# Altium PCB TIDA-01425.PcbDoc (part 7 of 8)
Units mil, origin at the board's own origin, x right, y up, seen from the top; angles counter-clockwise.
Board outline 7000 x 3600 mil, 6 copper layers (Layer 1 - Top Layer, Layer 2 - GND, Layer 3 - Signal / PWR, Layer 4 - Signal / PWR, Layer 5 - PWR, Layer 6 - Bottom Layer), stack 60.4 mil thick; 495 components, 307 nets, 2058 pads, 1870 vias.
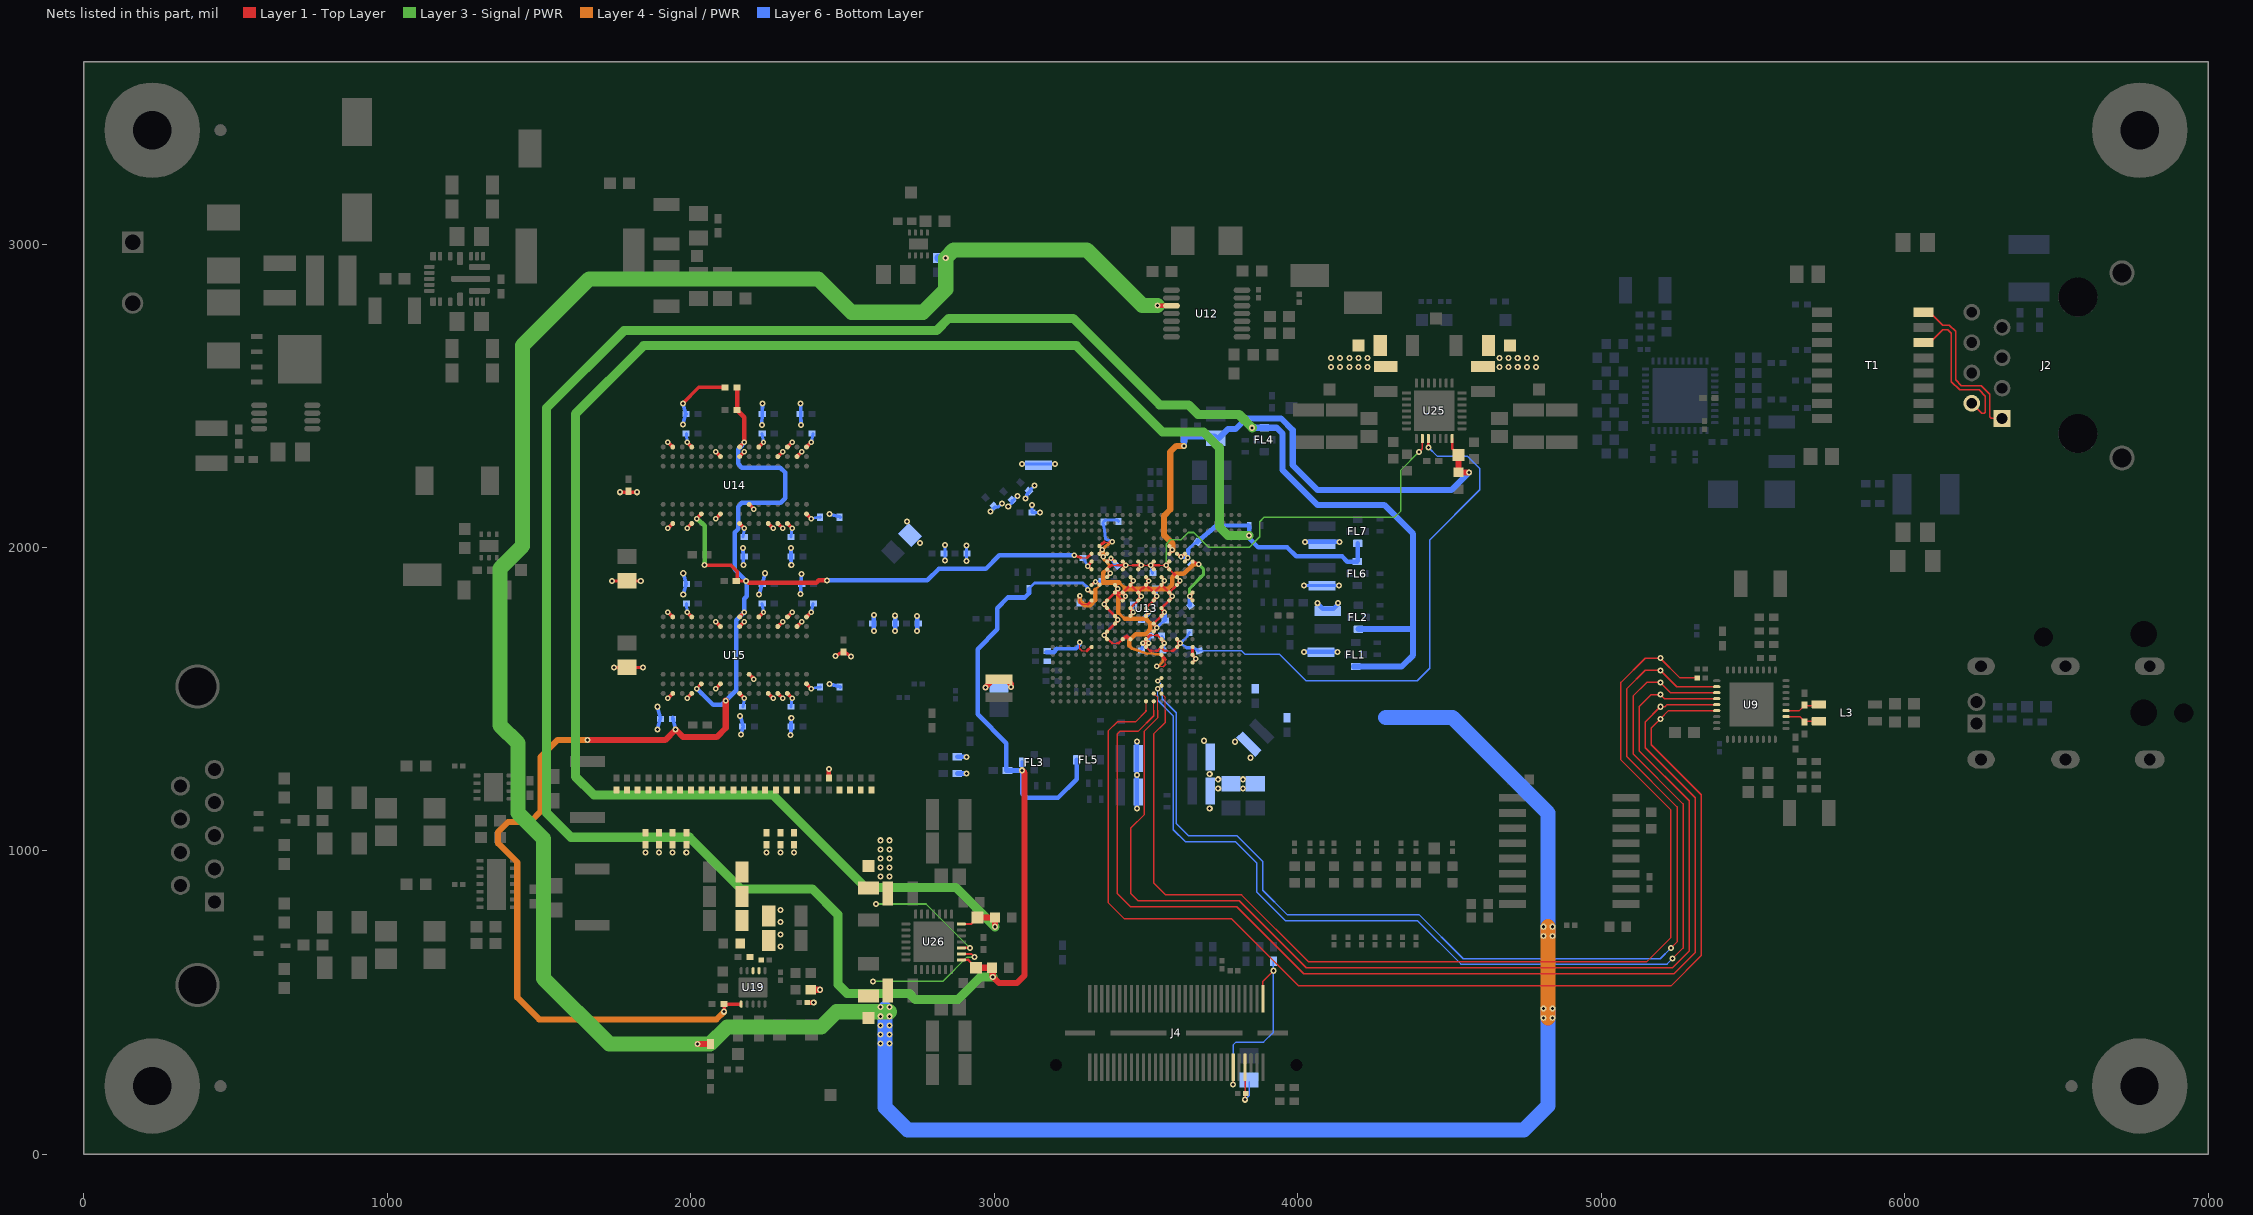
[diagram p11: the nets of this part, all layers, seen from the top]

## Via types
v1: diameter 20, hole 10, Layer 1 - Top Layer to Layer 6 - Bottom Layer, tented both sides, 1119 vias
v2: diameter 20, hole 9.99, Layer 1 - Top Layer to Layer 6 - Bottom Layer, tented both sides, 298 vias
v3: diameter 18, hole 7.99, Layer 1 - Top Layer to Layer 6 - Bottom Layer, tented both sides, 203 vias
v4: diameter 18, hole 8, Layer 1 - Top Layer to Layer 6 - Bottom Layer, tented both sides, 177 vias
v5: diameter 19.68, hole 7.87, Layer 1 - Top Layer to Layer 6 - Bottom Layer, tented both sides, 41 vias
v6: diameter 20, hole 10, Layer 1 - Top Layer to Layer 6 - Bottom Layer, 27 vias
v7: diameter 19.68, hole 7.87, Layer 1 - Top Layer to Layer 6 - Bottom Layer, 5 vias

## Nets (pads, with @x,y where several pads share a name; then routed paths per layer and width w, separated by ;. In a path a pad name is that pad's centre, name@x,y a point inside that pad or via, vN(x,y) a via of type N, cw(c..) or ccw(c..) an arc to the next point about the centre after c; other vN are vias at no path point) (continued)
TRD1_N: L3.2 U9.13 U10.1 | length 114.8
  Layer 1 - Top Layer w5: U9.13@5609.17,1462.32 5653.31,1462.32 5670,1479 L3.2@5713.92,1479
  Layer 1 - Top Layer w8: L3.2@5715.24,1480.32 L3.2@5717.48,1482.56
TRD1_P: L3.3 U9.12 U11.1 | length 114.6
  Layer 1 - Top Layer w5: U9.12@5609.17,1442.63 5654.37,1442.63 5669.56,1427.44 L3.3@5717.48,1427.44
TRSTPD: J4.8 R57.2 R58.2 | length 172.8
  Layer 1 - Top Layer w5: v1(3826.38,180) J4.8@3826.38,287.21
  Layer 6 - Bottom Layer w5: v1(3826.38,180) 3840,193.62 R58.2@3840,240
TX+: J2.1 T1.16 | length 541.1
  Layer 1 - Top Layer w4.4: T1.16@6062.52,2775 6083,2775 6126,2732 6147.8,2732 6168,2711.8 6168,2552 6187,2533 6251.8,2533 6280,2504.8 6280,2430 6285,2425 J2.1@6321.26,2425
TX-: J2.2 T1.14 | length 518.7
  Layer 1 - Top Layer w4.4: T1.14@6062.52,2675 6082,2675 6125,2718 6142,2718 6154,2706 6154,2546.2 6181.2,2519 6246,2519 6266,2499 6266,2446 6262,2442 6254.26,2442 J2.2@6221.26,2475
TX_CLK_1: R25.1 U13.B11 | length 3711.9
  Layer 1 - Top Layer w4: U13.B11@3551.18,1518.5 3563.87,1505.81 3563.87,1464
  Layer 1 - Top Layer w5: 3563.87,1464 3563.87,1423.87 3525,1385 3525,895 3565,855 3815,855 4036,634 5149,634 5230,715 5230,1135 5065,1300 5065,1555 5145,1635 v6(5195,1635) 5260,1570 R25.1@5317.01,1570
TX_CTRL_1: U9.29 U13.D11 | length 3671
  Layer 1 - Top Layer w4: v3(3538.6,1559.9) U13.D11@3551.18,1569.69
  Layer 1 - Top Layer w5: v1(5230,680) 5250,700 5250,1145 5085,1310 5085,1535 5145,1595 v6(5195,1595) 5248.94,1541.06 U9.29@5380.83,1541.06
  Layer 6 - Bottom Layer w4: v3(3538.6,1559.9) 3539.1,1559.9 3553.59,1545.41 3553.59,1523.6
  Layer 6 - Bottom Layer w5: 3553.59,1523.6 3553.59,1501.41 3600,1455 3600,1090 3640,1050 3800,1050 3885,965 3885,870 3965,790 4400,790 4545.36,644.64 5194.64,644.64 v1(5230,680)
TX_D0_1: U9.33 U13.A13 | length 3918.1
  Layer 1 - Top Layer w4: 3500,1464 U13.A13@3500,1492.91
  Layer 1 - Top Layer w5: 3500,1464 3500,1460 3465,1425 3405,1425 3375,1395 3375,830 3429,776 3782.28,776 4003.28,555 5230,555 5330,655 5330,1185 5165,1350 5165,1405 v6(5195,1435) 5222.31,1462.32 U9.33@5380.83,1462.32
TX_D1_1: U9.32 U13.A12 | length 3849.5
  Layer 1 - Top Layer w4: 3525.59,1464 U13.A12@3525.59,1492.91
  Layer 1 - Top Layer w5: 3525.59,1464 3525.59,1445.59 3475,1395 3415,1395 3405,1385 3405,860 3449,816 3798.85,816 4019.85,595 5240,595 5310,665 5310,1175 5145,1340 5145,1425 v6(5195,1475) 5210,1475 5217,1482 U9.32@5380.83,1482
TX_D2_1: U9.31 U13.B12 | length 3815.8
  Layer 1 - Top Layer w4: U13.B12@3525.59,1518.5 3538.28,1505.81 3538.28,1464
  Layer 1 - Top Layer w5: 3538.28,1464 3538.28,1438.28 3495,1395 3495,1120 3450,1075 3450,860 3474,836 3807.13,836 4028.13,615 5235,615 5290,670 5290,1165 5125,1330 5125,1475 5165,1515 v6(5195,1515) 5208.31,1501.68 U9.31@5380.83,1501.68
TX_D3_1: U9.30 U13.C11 | length 3649.3
  Layer 1 - Top Layer w4: v3(3538.6,1534) U13.C11@3551.18,1544.09
  Layer 1 - Top Layer w5: v1(5235,645) 5270,680 5270,1155 5105,1320 5105,1510 5150,1555 v6(5195,1555) 5228.63,1521.37 U9.30@5380.83,1521.37
  Layer 6 - Bottom Layer w4: 3538.6,1512.06 v3(3538.6,1534)
  Layer 6 - Bottom Layer w5: 3538.6,1512.06 3538.6,1496.4 3590,1445 3590,1070 3630,1030 3795,1030 3865,960 3865,865 3960,770 4395,770 4538.03,626.97 5216.97,626.97 v1(5235,645)
VDA_PHY_1V8: C59.1 C64.1 C268.1 FL6.1 FL7.1 TP62.1 U13.W8 U13.Y8 U13.Y9 U26.7 | length 6491.1
  Layer 1 - Top Layer w8: U26.7@2891.54,759.06 2924.06,759.06 TP62.1@2945,780
  Layer 1 - Top Layer w10: U13.Y9@3602.41,1979.19 v3(3615.3,1969.2) 3627.94,1979.15 3628,1979.2 v3(3638,1966.5) U13.W8@3628,1953.6
  Layer 1 - Top Layer w20: TP62.1@2945,780 C268.1@3002.44,780 v2(3002.44,750)
  Layer 3 - Signal / PWR w30: v2(3002.44,750) 2872.44,880 2575,880 2270.43,1184.57 1680.43,1184.57 1620,1245 1620,2440 1845,2665 3270,2665 3555,2380 3690,2380 3741.59,2328.41 3741.59,2068.41 3770,2040 v1(3840,2040)
  Layer 6 - Bottom Layer w10: 3638.5,1992 3642.3,1997.8 3656.5,2010.2 3668,2018.1 C59.1@3668.28,2017.79
  Layer 6 - Bottom Layer w15: v3(3615.3,1969.2) v3(3638,1966.5) 3638.5,1992 ; C59.1@3668.28,2017.79 3668.92,2018.32 3733.1,2072.2 3834.98,2072.79 3836.6,2072.8 3840,2069.4 3840,2030 3870,2000 3966,2000 3995,1971 4146,1971 4163.63,1953.37 FL6.1@4196,1953.37 4198,1955.37 FL7.1@4198,2013.63
VDA_PLL_1V8: C32.1 C33.1 C267.1 FL1.1 FL2.1 FL3.1 FL4.1 FL5.1 TP61.1 U13.R20 U26.1 | length 9704.2
  Layer 1 - Top Layer w8: U26.1@2891.54,640.94 2914.06,640.94 TP61.1@2940,615 TP61.1@2945,615
  Layer 1 - Top Layer w10: v3(3308,1860.8) U13.R20@3320.8,1851.2
  Layer 1 - Top Layer w20: TP61.1@2945,615 C267.1@2992.44,615 2995,612.44 v2(2995,585) 3015,565 3075,565 3100,590 3100,1257.4 v2(3091.7,1265.7)
  Layer 3 - Signal / PWR w30: v2(2995,585) 2955,585 2880,510 2740,510 2720,530 2515,530 2485,560 2485,790 2400,875 2165,875 1995,1045 1605,1045 1525,1125 1525,2460 1780,2715 2810,2715 2850,2755 3260,2755 3545,2470 3640,2470 3672,2438 3806.37,2438 v1(3850,2394.37)
  Layer 6 - Bottom Layer w10: v2(3091.7,1265.7) FL3.1@3091.7,1295 ; C33.1@3114.6,1864.6 3132.81,1882.81 3292.24,1882.81 3308,1867.05 v3(3308,1860.8)
  Layer 6 - Bottom Layer w15: C33.1@3114.6,1864.6 3114.6,1849.6 3100,1835 3045,1835 3010,1800 3010,1730 2945,1665 2945,1450 3040,1355 3040,1265 3091,1265 v2(3091.7,1265.7) 3091.7,1188.3 3105,1175 3210,1175 3271.63,1236.63 FL5.1@3271.63,1300
  Layer 6 - Bottom Layer w20: v1(3850,2394.37) FL4.1@3890,2394.37 3930.63,2394.37 3950,2375 3950,2255 4065,2140 4285,2140 4380,2045 4380,1730.63 FL2.1@4200,1730.63 ; FL1.1@4185,1607.63 FL1.1@4191,1607.63 4342.63,1607.63 4380,1645 4380,1727.63
VDA_USB_3V3: C49.1 C58.1 C60.1 C250.1 TP54.1 U13.AA10 U13.Y10 U25.7 | length 1768
  Layer 1 - Top Layer w8: U25.7@4509.06,2358.46 4509.06,2325.94 TP54.1@4530,2305
  Layer 1 - Top Layer w10: U13.Y10@3576.77,1979.13 v3(3586.8,1992.2) U13.AA10@3576.77,2004.72
  Layer 1 - Top Layer w20: TP54.1@4530,2305 C250.1@4530,2247.56 v2(4565,2247.56)
  Layer 4 - Signal / PWR w20: v3(3586.8,1992.2) 3586.8,2013.2 3560,2040 3560,2105 3580,2125 3580,2315 3600,2335 v2(3625,2335)
  Layer 6 - Bottom Layer w20: v2(3625,2335) C49.1@3625,2361.38 ; C49.1@3625,2361.38 3628.62,2365 C58.1@3670,2365 3725,2365 C60.1@3730,2360 3740,2360 3770,2390 3795,2390 3830,2425 3945,2425 3983.5,2386.5 3983.5,2271.5 4065,2190 4507.44,2190 v2(4565,2247.56)
VDD_CORE_AVS: C9.1 C10.1 C21.1 C27.1 C94.1 C95.1 C96.1 C97.1 C102.1 C240.1 L2.2 TP51.1 U13.J15 U13.J16 U13.J18 U13.K12 U13.K18 U13.L12 U13.L17 U13.M11 U13.M13 U13.M15 U13.M17 U13.N11 U13.N13 U13.N15 U13.N18 U13.P10 U13.P12 U13.P14 U13.P16 U13.P18 U13.R10 U13.R12 U13.R14 U13.R16 U13.R17 U13.T9 U13.T11 U13.T13 U13.T15 U13.T17 U13.U9 U13.U11 U13.U13 U13.U15 U13.U18 U13.V10 U13.V12 U13.V14 U13.V16 U13.V18 U13.W10 U13.W12 U13.W14 U13.W16 U25.2 | length 3423.4
  Layer 1 - Top Layer w4: 3389.16,1684.35 3389.55,1684.74 3405.73,1684.74 ; 3389.66,1940.76 3405,1940.76 ; v3(3433.3,1940.9) 3433.35,1940.85 3456.91,1940.85 ; v3@3492.2,1940.8 v3@3507.4,1940.8 ; U13.R12@3525.59,1851.18 3525.68,1851.09 3535,1841.77 v3(3535,1838.5) ; 3543.22,1940.8 v3@3558.5,1940.8
  Layer 1 - Top Layer w6: v2(4400,2315) 4410.63,2325.63 U25.2@4410.63,2358.46
  Layer 1 - Top Layer w8: U13.J18@3372.05,1697.64 3389.15,1684.35 ; U13.K18@3372.05,1723.23 U13.L17@3397.64,1748.82 ; U13.N18@3372.05,1800 U13.M17@3397.64,1774.41 ; U13.P18@3372.05,1825.59 U13.R17@3397.64,1851.18 ; U13.V18@3372.05,1927.95 3384.86,1940.76 3389.66,1940.76 ; 3405,1940.76 3433.16,1940.76 v3(3433.3,1940.9) v3@3440.68,1940.9 ; 3405.73,1684.74 3410.33,1684.74 U13.J16@3423.23,1697.64 ; U13.R16@3423.23,1851.18 U13.R17@3397.64,1851.18 ; U13.R16@3423.25,1851.2 U13.T15@3448.82,1876.77 U13.R14@3474.41,1851.18 U13.T13@3500,1876.77 U13.R12@3525.59,1851.18 U13.T11@3551.18,1876.77 U13.R10@3576.77,1851.18 U13.R10@3576.77,1851.18 U13.T9@3602.36,1876.77 ; v3(3432.5,1838.5) 3432.5,1834.86 U13.P16@3423.23,1825.59 U13.R17@3397.64,1851.18 ; U13.N15@3448.82,1800 U13.P14@3474.41,1825.59 ; 3456.91,1940.85 v3(3484.2,1940.8) v3(3484.2,1940.8) v3@3492.2,1940.8 ; U13.N13@3500,1800 U13.P12@3525.59,1825.59 ; v3@3507.4,1940.8 v3(3516,1940.8) 3543.22,1940.8 ; U13.L12@3525.59,1748.82 U13.M11@3551.18,1774.41 ; U13.N11@3551.18,1800 U13.P10@3576.77,1825.59 ; v3@3558.5,1940.8 3558.6,1940.9 v3(3567.2,1940.9) ; U13.V10@3576.77,1927.95 3602.32,1902.4 U13.U9@3602.36,1902.36
  Layer 1 - Top Layer w10: U13.J18@3372.05,1697.64 v3(3362.3,1710.4) U13.K18@3372.05,1723.23 ; U13.U18@3372.05,1902.36 3382,1913.4 v3(3382,1915.1) U13.V18@3372.05,1927.95 ; U13.V16@3423.23,1927.95 v3(3433.3,1940.9) U13.W16@3423.23,1953.54 ; U13.T15@3448.82,1876.77 v3(3458.3,1889.8) U13.U15@3448.82,1902.36 ; U13.V14@3474.41,1927.95 v3(3484.2,1940.8) U13.W14@3474.43,1953.56 ; U13.T13@3500,1876.77 v3(3509.4,1889.4) U13.U13@3500,1902.36 ; U13.R12@3525.59,1851.18 3525.68,1851.09 v3(3535,1838.5) ; U13.V12@3525.59,1927.95 v3(3516,1940.8) U13.W12@3525.59,1953.54 ; U13.T11@3551.18,1876.77 v3(3560.9,1889.6) U13.U11@3551.18,1902.36 ; U13.V10@3576.77,1927.95 v3(3567.2,1940.9) U13.W10@3576.77,1953.54 ; U13.T9@3602.36,1876.77 v3(3612.06,1889.89) U13.U9@3602.36,1902.36
  Layer 1 - Top Layer w12: U13.N18@3372.05,1800 v3(3362,1813) U13.P18@3372.05,1825.59 ; U13.L17@3397.64,1748.82 v3(3407,1761.5) U13.M17@3397.64,1774.41 ; U13.R17@3397.64,1851.18 v3(3407,1864) U13.T17@3397.64,1876.77 ; U13.R16@3423.23,1851.18 v3(3432.5,1838.5) ; U13.J16@3423.23,1697.64 3436,1707 U13.J15@3448.82,1697.64 ; U13.M15@3448.82,1774.41 v3(3458.5,1787) U13.N15@3448.82,1800 ; U13.P14@3474.41,1825.59 v3(3483.7,1838.5) U13.R14@3474.41,1851.18 ; U13.M13@3500,1774.41 v3(3509.5,1787.5) U13.N13@3500,1800 ; U13.K12@3525.59,1723.23 v3(3535,1736) U13.L12@3525.59,1748.82 ; U13.P12@3525.59,1825.59 v3(3535,1838.5) ; U13.M11@3551.18,1774.41 v3(3561,1787) U13.N11@3551.18,1800 ; U13.P10@3576.77,1825.59 v3(3586.1,1838.5) U13.R10@3576.77,1851.18
  Layer 3 - Signal / PWR w5.25: v3(3567.2,1940.9) 3567.2,2012.2 3580,2025 3615,2025 3639.15,2049.15 3657.46,2049.15 3706.61,2000 3840,2000 3875,2035 3875,2085 3890,2100 4320,2100 4340,2120 4340,2255 v2(4400,2315)
  Layer 6 - Bottom Layer w10: C102.1@3457.5,1812.5 3457.53,1811.92 v3(3458.5,1787) ; v3(3516,1940.8) 3521.82,1915.8 C95.1@3522,1915 ; C97.1@3533,1863.5 v3(3535,1838.5) ; v3(3535,1736) 3545.15,1745.1 3554.04,1753.99 3555.07,1753.99 3562.83,1760.95 C96.1@3564,1762 ; v2(4021.2,1874.3) 4021.5,1874 v2(4136,1874)
  Layer 6 - Bottom Layer w15: C94.1@3488,1762 3509.5,1783.5 v3(3509.5,1787.5) ; v3(3561,1787) 3561,1765 C96.1@3564,1762 ; v2@4021.2,1655.8 v2(4131.6,1655.8) ; v1@4024,2018.1 v2(4137.1,2018.1) ; v2(4064.8,1816.2) 4083,1798 4117.9,1798 4132.9,1813 v2(4132.9,1817.3)
  other v1: 4024,2018
  other v2: 4021,1656 4110,2595 4140,2595 4170,2595 4200,2595 4230,2595 4110,2625 4140,2625 4170,2625 4200,2625 4230,2625
VDD_DDR_1V35: C61.1 C63.1 C65.1 C66.1 C67.1 C68.1 C69.1 C70.1 C71.1 C72.1 C73.1 C74.1 C75.1 C76.1 C77.1 C78.1 C80.1 C81.1 C82.1 C83.1 C84.1 C85.1 C86.1 C87.1 C88.1 C89.1 C90.1 C91.1 C92.1 C93.1 C111.1 C113.1 C117.1 C118.1 C119.1 C123.1 C133.1 C134.1 C135.1 C136.1 C137.1 C138.1 C139.1 C140.1 C143.2 C144.2 C146.2 C148.2 C162.2 C181.2 C182.2 C192.1 C196.1 C197.1 C198.1 C200.1 C263.1 L14.2 R75.1 TP60.1 U13.T19 U13.T20 U13.V20 U13.W17 U13.W18 U13.W20 U14.A1 U14.A8 U14.B2 U14.C1 U14.C9 U14.D2 U14.D9 U14.E9 U14.F1 U14.G7 U14.H2 U14.H9 U14.K2 U14.K8 U14.N1 U14.N9 U14.R1 U14.R9 U15.A1 U15.A8 U15.B2 U15.C1 U15.C9 U15.D2 U15.D9 U15.E9 U15.F1 U15.G7 U15.H2 U15.H9 U15.K2 U15.K8 U15.N1 U15.N9 U15.R1 U15.R9 U19.2 U26.3 | length 3653.1
  Layer 1 - Top Layer w8: U26.3@2891.54,680.31 v2(2920,680.31)
  Layer 1 - Top Layer w10: v1(1740,1890) v1(1835,1890) ; v1(1747.5,1604.5) v1(1842.5,1604.5) ; U13.V20@3320.8,1928 3308.3,1938 v3(3308.3,1938.3) U13.W20@3320.87,1953.54 ; U13.T20@3320.87,1876.77 v3(3333.6,1886.7) U13.T19@3346.46,1876.77 ; U13.W18@3372.05,1953.54 3372.05,1953.7 v3(3384.7,1963.7) U13.W17@3397.6,1953.6
  Layer 1 - Top Layer w12: v1(1767,2182) 1795,2182.5 v1(1823,2182) ; v4(1924.54,1503.27) U15.R9@1940.28,1519.02 ; v4(1924.54,1786.72) U15.R1@1940.28,1770.98 ; v4(1924.54,2063.27) U14.R9@1940.28,2079.02 ; v4(1924.54,2346.72) U14.R1@1940.28,2330.98 ; v1(1973.94,2475) 2026.44,2527.5 C61.1@2111.44,2527.5 ; v4(1987.53,1503.27) U15.N9@2003.27,1519.02 ; v4(1987.53,1786.72) U15.N1@2003.27,1770.98 ; v4(1987.53,2063.27) U14.N9@2003.27,2079.02 ; v4(1987.53,2346.72) U14.N1@2003.27,2330.98 ; v4(2082.02,1534.77) U15.K8@2097.76,1550.51 ; v4(2082.02,1755.22) U15.K2@2097.76,1739.49 ; v4(2082.02,2094.77) U14.K8@2097.76,2110.51 ; v4(2082.02,2315.22) U14.K2@2097.76,2299.49 ; U15.H9@2160.75,1519.01 v4(2176.49,1503.27) ; U15.H2@2160.75,1739.48 v4(2176.49,1755.22) ; U14.H9@2160.75,2079.01 v4(2176.49,2063.27) ; U14.H2@2160.75,2299.48 v4(2176.49,2315.22) ; U15.G7@2192.24,1582.01 v4(2207.98,1566.26) ; U14.G7@2192.24,2142.01 v4(2207.98,2126.26) ; U15.F1@2223.74,1770.98 v4(2239.49,1786.73) ; U14.F1@2223.74,2330.98 v4(2239.49,2346.73) ; U15.E9@2255.24,1519.02 v4(2270.98,1503.27) ; U14.E9@2255.24,2079.02 v4(2270.98,2063.27) ; U15.D9@2286.73,1519.02 v4(2302.47,1503.27) ; U15.D2@2286.73,1739.49 v4(2302.47,1755.22) ; U14.D9@2286.73,2079.02 v4(2302.47,2063.27) ; U14.D2@2286.73,2299.49 v4(2302.47,2315.22) ; U15.C9@2318.23,1519.02 v4(2333.97,1503.27) ; U15.C1@2318.23,1770.98 v4(2333.97,1786.72) ; U14.C9@2318.23,2079.02 v4(2333.97,2063.27) ; U14.C1@2318.23,2330.98 v4(2333.97,2346.72) ; U15.B2@2349.72,1739.49 v4(2365.46,1755.22) ; U14.B2@2349.72,2299.49 v4(2365.46,2315.22) ; U15.A8@2381.22,1550.51 v4(2396.96,1534.77) ; U15.A1@2381.22,1770.98 v4(2396.97,1786.73) ; U14.A8@2381.22,2110.51 v4(2396.96,2094.77) ; U14.A1@2381.22,2330.98 v4(2396.97,2346.73) ; v1(2477,1642) 2501.9,1657.13 2502.5,1657.5 2503.85,1656.63 v1(2528,1641)
  Layer 1 - Top Layer w15: C192.1@2383,500 v1(2405,500) ; C200.1@2455,1239.68 v1(2455,1270)
  Layer 1 - Top Layer w20: R75.1@2395,542.44 v1(2425,542.44)
  Layer 3 - Signal / PWR w5: v1(2610,825) 2775.31,825 v2(2920,680.31)
  Layer 6 - Bottom Layer w10: C83.1@1985.01,1814.97 v4(1987.53,1786.72) ; C67.1@1985,2375 v4(1987.53,2346.72) ; C80.1@2172.5,1475 v4(2176.49,1503.27) ; C65.1@2172.5,2035 2172.57,2035.49 v4(2176.49,2063.27) ; C82.1@2235.01,1814.95 v4(2239.49,1786.73) ; C68.1@2235.01,2374.95 v4(2239.49,2346.73) ; C85.1@2330.01,1475.04 v4(2333.97,1503.27) ; C63.1@2330.01,2035.04 v4(2333.97,2063.27) ; v4(2396.96,1534.77) 2425.02,1539.57 C84.1@2427.5,1540 ; v4(2396.97,1786.73) C81.1@2402.5,1815 ; v4(2396.96,2094.77) 2425.02,2099.57 C66.1@2427.5,2100 ; v4(2396.97,2346.73) 2402.4,2374.47 C69.1@2402.5,2375 ; v2(2838,1957) v2(2838,2008) ; v2(2908,1956) v2(2908,2007) ; v2(2987,2118) 3002.86,2133.86 3013.86,2133.86 v2(3025,2145) ; v2(3046,2135) 3058.14,2147.14 3058.14,2154.86 3062.86,2154.86 v2(3077,2169) ; v2(3092,2275.5) v2@3200,2275.5 ; v2(3103,2162) 3107,2166 3107,2175 3116.86,2184.86 3117.14,2184.86 3117.14,2188.14 v2(3133,2204) ; v2(3124.68,2140) C133.1@3124.68,2115 v2(3150.68,2115) ; C138.1@3293,1965 v3(3308.3,1938.3) ; v3(3333.6,1886.7) 3355.32,1888.93 C139.1@3356,1889 ; v3(3384.7,1963.7) 3392.58,1951.39 3394.26,1948.76 3396.65,1945.03 3397.71,1943.37 3398.01,1942.91 3398.3,1942.45 3398.79,1941.69 3399.35,1940.81 3399.86,1940.02 3400,1939.8 3400.76,1938.61 3400.9,1938.4 C140.1@3401.08,1938.11
  Layer 6 - Bottom Layer w12: v1(1890,1400) 1898.85,1435.37 1900,1440 v1(1890,1475) ; v1(1973.94,2405) 1983.94,2440 v1(1973.94,2475) ; v1(1975,1845) 1985,1880 v1(1975,1915) ; v1(2162.5,1445) C93.1@2172.34,1410.58 ; v1(2164.99,1383.72) C93.1@2172.34,1409.42 ; v1(2172,1998) 2172.5,1970 2172.5,1969.94 v1(2173,1942) ; v1(2224.69,1845) 2234.69,1880 2234.73,1880.17 v1(2244.69,1915) ; v1(2234,2404) 2235,2440 v1(2236,2475) ; v1(2329,1382) 2330,1410 v1(2331,1438) ; v1(2330,1998) 2330,1970 v1(2331,1942) ; v1(2362,1847) 2362.5,1880 2362.52,1880.21 v1(2365,1913) ; v1(2362,2475) C77.1@2362.5,2440.03 ; C77.1@2362.5,2440 v1(2363,2404) ; v1(2457.5,1550) 2490.27,1540.63 C88.1@2492.5,1540 ; v1(2457.5,2110) 2490.27,2100.63 C71.1@2492.5,2100
  Layer 6 - Bottom Layer w15: v2(2603,1725) v2(2603,1777) ; v2(2673,1725) v2(2673,1775) ; v2(2746,1725) v2(2746,1774)
  other v1: 2295,685 2295,725 2295,765 2295,805 1850,995 1895,995 1940,995 1985,995 2250,995 2295,995 2340,995
  other v2: 2625,915 2655,915 2625,945 2655,945 2625,975 2655,975 2625,1005 2655,1005 2625,1035 2655,1035 2755,2015 2712,2085 3200,2275
VDD_DSP_AVS: C98.1 C99.1 C100.1 C101.1 C103.1 C104.1 C105.1 C106.1 C107.1 C108.1 C109.1 C114.1 C115.1 C244.1 L12.2 TP53.1 U13.H9 U13.H11 U13.H13 U13.J9 U13.J11 U13.J13 U25.3 | length 2536.3
  Layer 1 - Top Layer w4: 3517.26,1659.6 3517.5,1659.36 3533.68,1659.36 ; 3517.6,1710.44 3533.58,1710.44 ; 3568.78,1659.26 3584.76,1659.26
  Layer 1 - Top Layer w8: U13.H13@3500,1672.05 3512.45,1659.6 3517.26,1659.6 ; 3512.1,1709.8 3512.74,1710.44 3517.6,1710.44 ; 3533.58,1710.44 3538.38,1710.44 U13.J11@3551.18,1697.64 ; 3533.68,1659.36 3538.49,1659.36 U13.H11@3551.18,1672.05 ; v3(3560.5,1685) 3560.5,1681.37 U13.H11@3551.18,1672.05 ; 3568.78,1659.26 3560.78,1659.26 3551.18,1668.86 U13.H11@3551.18,1672.05 ; 3584.76,1659.26 3589.57,1659.26 U13.H9@3602.36,1672.05 ; v2(4430.31,2330) U25.3@4430.31,2358.46
  Layer 1 - Top Layer w10: U13.H13@3500,1672.05 3500,1675 v3(3490,1685) ; v3(3509.5,1685) v3(3490,1685) ; 3512.1,1709.8 3500,1697.7 U13.J13@3500,1697.64 3500,1695 v3(3490,1685)
  Layer 1 - Top Layer w12: U13.H13@3500,1672.05 v3(3509.5,1685) U13.J13@3500,1697.64 ; U13.J11@3551.18,1697.64 v3(3560.5,1685) ; U13.H9@3602.36,1672.05 v3(3612.2,1684.8) U13.J9@3602.36,1697.64
  Layer 6 - Bottom Layer w5: C104.1@3676,1660 3814,1660 3826,1648 3940,1648 4027,1561 4394,1561 4435,1602 4435,2025 4600,2190 4600,2260 4560,2300 4460.31,2300 v2(4430.31,2330)
  Layer 6 - Bottom Layer w6: 3622.63,1692.63 3624.31,1694.31 3624.83,1694.31 3634.19,1703.67 3634.19,1704.19 3635.85,1705.85
  Layer 6 - Bottom Layer w8: v3(3612.2,1684.8) 3612.35,1684.21 3631.9,1671.45
  Layer 6 - Bottom Layer w10: C105.1@3485.2,1661.6 v3(3490,1685) ; v3(3509.5,1685) C115.1@3512,1707.2 ; C103.1@3552.4,1706.6 v3(3560.5,1685) C106.1@3556,1662.8 ; v3(3612.2,1684.8) 3622.63,1692.63 ; 3631.9,1671.45 3633.84,1669.51 3657.98,1669.51 3664.44,1665.04 C104.1@3673.57,1658.73 ; 3635.85,1705.85 C114.1@3642.78,1719
  Layer 6 - Bottom Layer w15: v2(3470,1140) v2(3470,1250) v2(3470,1360)
  other v2: 3710,1140 3738,1205 3820,1205 3738,1236 3820,1236 3710,1253 3845,1307 3793,1359.67 3691,1363 4665,2595 4695,2595 4725,2595 4755,2595 4785,2595 4665,2625 4695,2625 4725,2625 4755,2625 4785,2625
VDDR_VREF: C61.2 C62.1 C78.2 C79.1 C190.1 U13.Y20 U14.H1 U14.M8 U15.H1 U15.M8 U19.6 | length 5640.5
  Layer 1 - Top Layer w4: 3285.19,1966.3 3305.12,1966.3
  Layer 1 - Top Layer w10: v4(2019.02,1534.77) U15.M8@2034.76,1550.51 ; C79.1@2152.5,1890 v1(2182,1890) ; v3(3264,1973.9) 3285.19,1966.3 ; 3305.12,1966.3 U13.Y20@3320.87,1979.13
  Layer 1 - Top Layer w12: v4(2019.02,2094.77) U14.M8@2034.76,2110.51 ; v1(2045.1,1941.6) 2132.7,1941.6 2152.5,1921.8 C79.1@2152.5,1890 ; v1(2109.69,470) C190.1@2109.69,495 ; C190.1@2109.8,494.88 U19.6@2164,494.88 ; U15.H1@2160.75,1770.98 v4(2176.49,1786.72) ; U14.H1@2160.75,2330.98 v4(2176.49,2346.72)
  Layer 1 - Top Layer w15: C61.2@2152.5,2527.5 2152.5,2452.5 2176.49,2428.51 v4(2176.49,2346.72) ; v1(2182,1890) 2189,1883 2413.4,1883 2421.8,1891.4 v1(2448.4,1891.4)
  Layer 1 - Top Layer w20: v1(1660,1365) 1915.01,1365 v1(1950,1400) 1975,1375 2085,1375 2115,1405 v4(2115,1495)
  Layer 3 - Signal / PWR w15: v4(2019.02,2094.77) 2021.53,2094.77 2045.3,2071 2045.3,1941.8 v1(2045.1,1941.6)
  Layer 4 - Signal / PWR w20: v1(1660,1365) 1560,1365 1505,1310 1505,1130 1470,1095 1397.37,1095 1365,1062.63 1365,1025 1427.91,962.09 1427.91,517.09 1500,445 2084.69,445 v1(2109.69,470)
  Layer 6 - Bottom Layer w12: C78.2@1940,1440 1941.16,1435.37 v1(1950,1400)
  Layer 6 - Bottom Layer w15: v4(2019.02,1534.77) 2020.23,1534.77 2073.2,1481.8 2101.8,1481.8 v4(2115,1495) 2149.4,1529.4 2149.4,1759.63 v4(2176.49,1786.72) 2176.49,1831.49 2184,1839 2184,1888 v1(2182,1890) 2144.5,1927.5 2144.5,2049.4 2155.99,2060.89 2155.99,2134.76 2167.99,2146.76 2296,2146.76 2311,2161.76 2311,2247 2294.77,2263.23 2167.99,2263.23 2155.99,2275.23 2155.99,2323.72 2169,2336.73 2169,2339.23 v4(2176.49,2346.72) ; v1(2448.4,1891.4) 2779,1891.4 2817.7,1930.1 2972.6,1930.1 3016.4,1973.9 v3(3264,1973.9)
VDDR_VTT: C143.1 C144.1 C146.1 C148.1 C162.1 C181.1 C182.1 C185.1 C186.1 C187.1 C188.1 R62.2 R63.2 R64.1 R65.1 R66.2 R67.2 R68.2 R71.2 R72.2 R73.2 R74.2 R76.2 R77.2 R78.2 R80.2 R81.2 R82.2 R83.2 R84.2 R85.2 R86.2 R87.2 R88.2 U19.3
VDDS_1V8: C110.1 C112.1 C116.1 C122.1 C124.1 C125.1 C126.1 C127.1 C128.1 C129.1 C130.1 C158.1 C159.1 C259.1 L13.2 R93.2 R97.2 TP59.1 U12.3 U13.AA19 U13.F7 U13.G7 U13.G11 U13.H7 U13.H20 U13.P7 U13.P20 U13.R7 U13.W7 U13.Y18 U13.Y19 U26.2 | length 12939.6
  Layer 1 - Top Layer w4: v3(3281.2,1688.2) 3282.4,1687 3282.4,1665.5 ; 3282.4,1818.1 v3(3282.4,1841.5) ; 3287.7,1812.8 3308.7,1812.8 ; 3288.6,1659.3 3305.29,1659.3 ; 3362.34,2017.51 v3@3379.87,2017.51 ; v3@3535.08,1608.1 3558,1608.1 ; 3564,1614.1 3564,1630.38
  Layer 1 - Top Layer w6: U26.2@2891.54,660.63 2924.37,660.63 v2(2935,650) ; 3282.4,1665.5 3288.6,1659.3 ; 3282.4,1818.1 3287.7,1812.8 ; 3558,1608.1 3564,1614.1
  Layer 1 - Top Layer w8: v3@3379.87,2017.51 v3(3388.67,2019.26)
  Layer 1 - Top Layer w10: 3305.29,1659.3 U13.H20@3320.87,1672.05 ; 3308.7,1812.8 3320.87,1824.97 U13.P20@3320.87,1825.59 ; U13.AA19@3346.46,2004.72 3346.46,2005.16 3362.34,2017.51 ; v3(3356.2,1992) U13.Y19@3346.46,1979.13 v3(3359.3,1969.4) U13.Y18@3372.05,1979.13 ; v3(3534.8,1607.82) v3@3535.08,1608.1 ; U13.G11@3551.18,1646.46 3564,1630.38 ; U13.F7@3653.54,1620.87 v3(3664,1633.5) 3662.87,1634.64 3653.6,1646.4 U13.H7@3653.6,1672 ; U13.R7@3653.54,1851.18 v3(3644,1838.7) U13.P7@3653.59,1825.62 ; U13.W7@3653.6,1953.6 v3(3673.6,1944.9)
  Layer 1 - Top Layer w15: v1@3538.31,2796.51 U12.3@3583.86,2796.51
  Layer 1 - Top Layer w20: v1(2021.38,363.62) R97.2@2065,363.62 ; v2(2971,1539) 2997.53,1565.53 C110.1@3016,1565.53 3039.47,1565.53 3055.7,1549.3 v2(3055.7,1540)
  Layer 3 - Signal / PWR w5: v1(2600,570) 2830,570 2910,650 v2(2935,650)
  Layer 3 - Signal / PWR w10: v3(3644,1838.7) 3644,1865 3689,1910 3689,1929.5 v3(3673.6,1944.9)
  Layer 3 - Signal / PWR w50: 2655,470 2480,470 2430,420 2120,420 2063.62,363.62 v1(2021.38,363.62) 1731.38,363.62 1515,580 1515,1040 1430,1125 1430,1355 1371.16,1413.84 1371.16,1931.16 1445,2005 1445,2665 1665,2885 2420,2885 2530,2775 2765,2775 2840,2850 v2(2840,2953.78) 2866.22,2980 3305,2980 3487.9,2797.1 v1(3537.71,2797.1)
  Layer 4 - Signal / PWR w8: 3332.94,1860.9 3359.4,1884.5 ; 3409.07,1841.96 3429.26,1859.42 ; 3504.03,1649.55 3519.6,1651.7 3529.6,1647.9 3544.9,1647.9 3555.59,1639.36 3555.59,1623.66 3539.75,1607.82 v3(3534.8,1607.82)
  Layer 4 - Signal / PWR w10: 3361.3,1918.4 3361.3,1919.85 3380.65,1939.2 ; 3382.1,1939.2 3373.99,1947.31 3373.99,1948.46 3359.3,1963.16 v3(3359.3,1969.4) 3359.3,1988.9 v3(3356.2,1992) 3383.46,2019.26 v3(3388.67,2019.26) ; 3409.07,1784.88 3429.3,1764.65 ; 3411.95,1884.5 3429.26,1867.19 ; 3444.51,1676.51 3454.52,1666.5 3504.03,1649.55
  Layer 4 - Signal / PWR w15: v3(3282.4,1841.5) 3282.4,1821.6 3298,1810 3316.3,1810 3332.94,1826.64 3332.94,1860.9 ; 3361.3,1918.4 3359.4,1916.5 3359.4,1884.5 3411.95,1884.5 ; 3409.07,1784.88 3409.07,1841.96 ; 3429.26,1859.42 3429.26,1867.19 ; 3429.3,1764.65 3499.3,1764.65 3514.36,1749.59 3514.36,1730.06 3498.9,1714.6 3465.62,1714.6 3444.51,1693.49 3444.51,1676.51 ; 3431,1863 3572,1863 3586,1877 3586,1902 3597,1913 3625,1913 3656.9,1944.9 v3(3673.6,1944.9)
  Layer 4 - Signal / PWR w50: 4825,450 4825,750
  Layer 6 - Bottom Layer w10: C130.1@3170.5,1656.7 C130.1@3172.08,1655.12 ; 3281.2,1678.3 v3(3281.2,1688.2) ; v3(3356.2,1992) 3359.3,1988.9 v3(3359.3,1969.4) ; C126.1@3358,2081 3358.06,2080.72 3362.78,2057.43 3366,2028 v3(3388.67,2019.26) ; C126.1@3360,2084.32 3365.68,2090 3405.31,2090 C124.1@3410,2085.32 ; C128.1@3649.86,1943.41 3651.78,1943.53 v3(3673.6,1944.9)
  Layer 6 - Bottom Layer w12: 3206.4,1665.6 3268.5,1665.6 3281.2,1678.3
  Layer 6 - Bottom Layer w15: C122.1@2878.62,1255 v1(2908.62,1255) ; C116.1@2878.62,1310 v1(2908.62,1310) ; C130.1@3172.08,1655.12 3195.92,1655.12 3206.4,1665.6 ; C125.1@3643.68,1810.02 v3(3644,1838.7)
  Layer 6 - Bottom Layer w25: R93.2@2815,2953.78 v2(2840,2953.78)
  Layer 6 - Bottom Layer w50: 2640,480 2640,155 2715,80 4745,80 4825,160 4825,480 ; 4290,1440 4510,1440 4825,1125 4825,720
  other v1: 4810,450 4840,450 4810,480 4840,480 4810,720 4840,720 4810,750 4840,750
  other v2: 2625,365 2655,365 2625,395 2655,395 2625,425 2655,425 2625,455 2655,455 2625,485 2655,485
VREF_DBG: J4.1 J4.12 R49.1 | length 678.2
  Layer 1 - Top Layer w5: v1(3787.01,230) J4.12@3787.01,287.21 ; J4.1@3885.44,512.8 3885.44,570.44 v1(3920,605)
  Layer 6 - Bottom Layer w5: v1(3787.01,230) 3787.01,360 3797.01,370 3887.52,370 3920,402.48 v1(3920,605) R49.1@3920,636.38
pads on no net: FID1.1 FID2.1 FID3.1 FID4.1 FID5.1 FID6.1 H5.0 H6.0 H7.0 H8.0 J1.4 J1.5 J1.8 J1.10 J1.11 J2.ALIGN1 J2.ALIGN2 J3.MH1 J3.MH2 J3.MH3 J3.MH4 J4.10 J4.11 J4.14 J4.18 J4.20 J4.22 J4.24 J4.26 J4.28 J4.30 J4.32 J4.34 J4.36 J4.38 J4.40 J4.42 J4.44 J4.46 J4.48 J4.50 J4.52 J4.54 J4.55 J4.56 J4.59 J4.60 J4.MH1 J4.MH2 T1.4 T1.5 T1.12 T1.13 U1.9@1360,827.6 U1.9@1360,877.6 U2.9@1350,1185 U2.9@1350,1235 U3. U5.8 U5.9 U5.10 U5.21 U5.22 U5.27 U5.41@5201.73,2441.73 U5.41@5201.73,2500 U5.41@5201.73,2558.27 U5.41@5260,2441.73 U5.41@5260,2500 U5.41@5260,2558.27 U5.41@5318.27,2441.73 U5.41@5318.27,2500 U5.41@5318.27,2558.27 U9.4 U9.6 U9.9 U9.14 U9.16 U9.17 U9.18 U9.19 U9.20 U9.21 U9.34 U12.2 U12.4 U13.A4 U13.A5 U13.A6 U13.A14 U13.A15 U13.A16 U13.A17 U13.A18 U13.A19 U13.A20 U13.A21 U13.A22 U13.A23 U13.A24 U13.AA1 U13.AA2 U13.AA3 U13.AA4 U13.AA5 U13.AA6 U13.AA11 U13.AB1 U13.AB2 U13.AB6 U13.AB7 U13.AB9 U13.AB12 U13.AB15 U13.AC1 U13.AC2 U13.AC3 U13.AC4 U13.AC5 U13.AC6 U13.AC8 U13.AC10 U13.AC15 U13.AC16 U13.AD1 U13.AD2 U13.AD3 U13.AD4 U13.AD6 U13.AD7 U13.AD9 U13.AD10 U13.AD12 U13.AD13 U13.AD15 U13.AE2 U13.AE3 U13.AE5 U13.AE6 U13.AE8 U13.AE9 U13.AE11 U13.AE12 U13.AE14 U13.B5 U13.B6 U13.B14 U13.B15 U13.B16 U13.B17 U13.B18 U13.B19 U13.B20 U13.B21 U13.B22 U13.B23 U13.B24 U13.B25 U13.C5 U13.C6 U13.C14 U13.C16 U13.C17 U13.C19 U13.C20 U13.C23 U13.C24 U13.C25 U13.D6 U13.D7 U13.D14 U13.D16 U13.D17 U13.D19 U13.D20 U13.D23 U13.D24 U13.D25 U13.E7 U13.E16 U13.E17 U13.E19 U13.E24 U13.E25 U13.F3 U13.F6 U13.F16 U13.F20 U13.F23 U13.F24 U13.F25 U13.G1 U13.G3 U13.G20 U13.G21 U13.G24 U13.G25 U13.H1 U13.H2 U13.H6 U13.H24 U13.H25 U13.J1 U13.J2 U13.J24 U13.J25 U13.K1 U13.K2 U13.K3 U13.K4 U13.K20 U13.L1 U13.L2 U13.L3 U13.L6 U13.L19 U13.L20 U13.L24 U13.L25 U13.M1 U13.M2 U13.M24 U13.M25 U13.N22 U13.N23 U13.N24 U13.N25 U13.P5 U13.T1 U13.T2 U13.T3 U13.U1 U13.U2 U13.U3 U13.U4 U13.U5 U13.U6 U13.V1 U13.V2 U13.V3 U13.V4 U13.V5 U13.W1 U13.W2 U13.Y1 U13.Y2 U13.Y3 U13.Y4 U13.Y5 U14.J1 U14.J9 U14.L1 U14.L9 U14.M7 U14.T3 U14.T7 U15.J1 U15.J9 U15.L1 U15.L9 U15.M7 U15.T3 U15.T7 U16.4 U16.5 U16.6 U16.11 U16.12 U16.13 U17.4A U17.4B U17.8A U17.8B U17.9A U17.9B U17.9C U17.9D U17.10A U17.10B U17.14A U17.14B U17.17 U18.7@1317.28,2005 U18.7@1352.72,2005 U24.3 U24.5 U25.29A U25.29B U25.29C U25.29D U26.26 U26.29A U26.29B U26.29C U26.29D U27.0

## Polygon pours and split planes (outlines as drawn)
"RJ45 GND" on Layer 1 - Top Layer "Layer 1 - RJ45_GND" (solid, pour order 92): 6050,1915 6050,3510 6075,3535 6845,3535 6935,3445 6935,1990 6845,1900 6065,1900
GND on Layer 1 - Top Layer "Layer 1 - GND" (solid, remove dead copper, pour order 104): 20,20 6980,20 6980,2240 6980,2960 6980,3580 20,3580
"RJ45 GND" on Layer 2 - GND "Layer 2 - RJ45_GND" (solid, pour order 94): 6050,1915 6050,3510 6075,3535 6845,3535 6935,3445 6935,1990 6845,1900 6065,1900
GND on Layer 2 - GND "Layer 2 - GND" (solid, remove dead copper, pour order 106): 20,20 6980,20 6980,3580 20,3580
"RJ45 GND" on Layer 3 - Signal / PWR "Layer 3 - RJ45_GND" (solid, pour order 96): 6050,1915 6050,3510 6075,3535 6845,3535 6935,3445 6935,1990 6845,1900 6065,1900
VDD_CORE_AVS on Layer 3 - Signal / PWR "Layer 3 - VDD_CORE_AVS" (solid, remove dead copper, pour order 88): 3373,1916 3373,1844 3353,1824 3353,1808 3358,1803 3368,1803 3377,1794 3377,1755 3356,1734 3353,1731 3353,1723 3353,1706 3358,1701 3366,1701 3371,1706 3371,1718 3403,1750 3405,1752 3420,1752 3496,1752 3511,1737 3521,1727 3534,1727 3539,1727 3544,1732 3544,1740 3556,1752 3570,1766 3570,1788 3570,1809 3596,1835 3596,1861 3618,1883 3622,1887 3622,1891 3622,1895 3618,1899 3556,1899 3551,1894 3551,1883 3544,1876 3526,1876 3519,1883 3519,1894 3514,1899 3505,1899 3500,1894 3500,1883 3493,1876 3475,1876 3468,1883 3468,1894 3463,1899 3454,1899 3449,1894 3449,1887 3438,1876 3426,1876 3421,1881 3398,1904 3398,1917 3398,1918 3392,1924 3378,1924 3373,1919
SYS_3V3 on Layer 3 - Signal / PWR "Layer 3 - SYS_3V3" (solid, remove dead copper, pour order 86): 4400,2780 4200,2780 4045,2625 4025,2605 4025,2515 4025,2475.15 4024.85,2475 4875,2475 4875.09,2474.91 4875.09,2604.91 4875,2605 4700,2780 4640,2780
GND on Layer 3 - Signal / PWR "Layer 3 - GND" (solid, remove dead copper, pour order 108): 20,20 6980,20 6980,3580 20,3580
SW_3V3 on Layer 3 - Signal / PWR "Layer 3 - SW_3V3" (solid, remove dead copper, pour order 84): 2890,1590 2890,1665 2970,1745 2976,1751 3009,1751 3288,1751 3298,1761 3298,1792.77 3332,1826.77 3332,1923 3325,1930 3371.64,1976.64 3371.64,2033.92 3371.64,2066.64 3397.06,2092.06 3407.28,2092.06 3417.04,2101.82 3417.04,2112.04 3422.5,2117.5 3422.5,2187.5 3465,2230 3525,2230 3569.34,2230 3625.17,2285.83 3643,2285.83 3650.41,2278.41 3650.42,2148.93 3585.24,2083.76 3502,2083.76 3489.12,2070.88 3489.12,2044.12 3445.02,2000.02 3445.02,1960.02 3415,1930 3378,1930 3369,1921 3369,1877 3366,1874 3365.57,1873.57 3359.62,1873.57 3354.18,1873.57 3348.67,1868.06 3348.67,1804.33 3356,1797 3360,1797 3367,1790 3367,1784 3360,1777 3356,1777 3345,1766 3347,1764 3347,1712 3347,1675 3352,1670 3352.7,1669.3 3358.08,1669.3 3365.3,1669.3 3372,1676 3372,1687 3383.25,1698.25 3397.25,1698.25 3401,1702 3401,1718 3402,1719 3413,1730 3427.88,1730 3582,1730 3607,1755 3646,1794 3672.32,1794 3675,1794 3679,1790 3681.48,1787.52 3681.48,1772.51 3681.48,1726.47 3675,1720 3675,1657.75 3664.01,1646.75 3658.75,1646.75 3649,1637 3647.65,1638.35 3609.3,1638.35 3605.38,1638.35 3597.02,1630 3594.03,1627 3580,1627 3569.34,1627 3557.62,1638.72 3549.29,1647.05 3515.91,1647.05 3459.26,1647.05 3454.33,1642.12 3447.29,1635.09 3394.66,1635.09 3383.4,1646.35 3381.8,1646.35 3356.35,1646.35 3340,1630 3310.01,1630 3245,1565 2915,1565
"RJ45 GND" on Layer 4 - Signal / PWR "Layer 4 - RJ45_GND" (solid, pour order 98): 6050,1915 6050,3510 6075,3535 6845,3535 6935,3445 6935,1990 6845,1900 6065,1900
SW_3V3 on Layer 4 - Signal / PWR "Layer 4 - SW_3V3" (solid, remove dead copper, pour order 72): 3645,1675 3605,1715 3605,1815 3605,1871 3685,1951 3685,2015 3625,2075 3625,2280 3635,2290 3675,2290 3695,2310 3695,3150 3725.47,3180.47 4024.52,3180.47 4669.53,3180.48 4730,3120 4730,2835 4690,2795 4235,2795 3940,2500 3940,2380 3940,1960 3860,1880 3705,1880 3680,1855 3680,1700 3705,1675 3815,1675 3825,1665 3857.27,1632.73 4191,1632.73 4202.27,1632.73 4220,1615 4220,1515 4190,1485 3875,1485 3803.02,1556.98 3803.02,1566.68 3803.02,1603.11 3775.23,1630.9 3729.1,1630.9 3714,1646 3692,1646 3681,1657 3663,1657
VDD_DSP_AVS on Layer 4 - Signal / PWR "Layer 4 - VDD_DSP_AVS" (solid, remove dead copper, pour order 74): 3475,1690 3475,1697 3478,1700 3480,1702 3486,1702 3506,1702 3516,1712 3528,1724 3568,1724 3589,1724 3626,1687 3661,1652 3666,1652 3675,1652 3684,1643 3693,1634 3693,1594 3693,1564 3716,1541 3751.71,1541 3761.98,1530.72 3761.98,1417.02 3826,1353 3859,1320 3940,1320 4285,1320 4404,1439 4404,2145 4486,2227 4486,2604 4559,2677 4870,2677 4926,2621 4926,1571 4430,1075 3491,1075 3454,1112 3454,1424.79 3551.7,1522.49 3551.7,1606.69 3565,1620 3565,1639.98 3548.06,1656.92 3488.08,1656.92 3478,1667 3475,1670 3475,1689
GND on Layer 4 - Signal / PWR "Layer 4 - GND" (solid, remove dead copper, pour order 110): 20,20 6980,20 6980,3580 20,3580
"RJ45 GND" on Layer 5 - PWR "Layer 5 - RJ45_GND" (solid, pour order 100): 6050,1915 6050,3510 6075,3535 6845,3535 6935,3445 6935,1990 6845,1900 6065,1900
VDD_DDR_1V35 on Layer 5 - PWR "Layer 5 - VDD_DDR_1V35" (solid, remove dead copper, pour order 46): 2665,1440 2685,1460 2735,1510 2865,1510 2880.01,1510 3090,1720 3285,1720 3285,1765.12 3349.88,1830 3349.88,1906.88 3404.21,1961.21 3491.21,1961.21 3495,1965 3495,2505 3375,2625 1920,2625 1770,2475 1615,2320 1615,630 1825,420 2350,420 2540,610 2540,750 2665,875
VDDS_1V8 on Layer 5 - PWR "Layer 5 - VDDS_1V8" (solid, remove dead copper, pour order 44): 3295,1710 3295,1670.2 3249.84,1625.05 2935,1310.2 2935,1270 2935,1240 2900,1205 2825,1205 2805,1185 2805,805 2835,775 2835,525 2665,355 2580,355 2550,385 2550,580 2625,655 2625,800 2685,860 2685,1430 2755,1500 2884.18,1500 3094.15,1709.98
VDD_DSP_AVS on Layer 5 - PWR "Layer 5 - VDD_DSP_AVS" (solid, remove dead copper, pour order 42): 4678,2677 4559,2677 4476,2594 4476,2381 4375,2280 4375,2195 4375,1755 4250,1630 3835,1630 3815,1650 3758,1707 3456.17,1707 3437.46,1688.3 3328.3,1688.3 3220,1580 3220,1150 3295,1075 4530,1075 4926,1471 4926,2621 4870,2677
VDD_CORE_AVS on Layer 5 - PWR "Layer 5 - VDD_CORE_AVS" (solid, remove dead copper, pour order 40): 3295,1696 3295,1762 3360,1827 3360,1905.99 3403.98,1949.98 3482.98,1949.98 3679,2146 3679,2602 3754.05,2677.05 4341.07,2677.05 4424.12,2594 4424.12,2377.88 4350.84,2304.61 4350.84,2210.34 4350.84,1789.84 4206,1645 3865,1645 3793,1717 3451.89,1717 3433.36,1698.47 3430.89,1696
GND on Layer 5 - PWR "Layer 5 - GND" (solid, remove dead copper, pour order 112): 20,20 6980,20 6980,3580 20,3580
SYS_5V0 on Layer 5 - PWR "Layer 5 - SYS_5V0" (solid, remove dead copper, pour order 78): 1600,855 1600,2325 1665,2390 1915,2640 2050,2640 3380,2640 3490,2530 3550,2470 3615,2470 3645,2470 3665,2490 3665,2590 3630,2625 3500,2755 2230,2755 1870,2755 1580,2465 1505,2390 1505,1985 1420,1900 1420,1795 1505,1710 1505,875 1525,855
SYS_3V3 on Layer 5 - PWR "Layer 5 - SYS_3V3" (solid, remove dead copper, pour order 80): 1490,2280 1490,1995 1405,1910 1405,1785 1430,1760 1490,1700 1490,1660 1490,840 1565,765 1600,730 1600,720 1600,620 1685,535 1815,405 1905,405 2505,405 2560,350 2570,340 2650,340 2679.61,340 2850,510.39 2850,660 2880,690 2880,710 2850,740 2850,785 2815,820 2805,830 2805,900 2805,1155 2825,1175 2840,1190 2910,1190 2965,1190 3100,1055 3100,570 3175,495 4030,495 4075,450 4075,380 4030,335 3180,335 3115,270 3025,180 2710,180 1535,180 1225,490 1225,1645 1090,1780 1090,2600 1365,2875 1520,3030 2170,3030 3720,3030 3795,3105 4870,3105 4925,3050 4925,2785 4870,2730 3550,2730 3510,2770 2170,2770 2140,2800 1985,2800 1955,2770 1860,2770 1815,2725 1490,2400
SW_3V3 on Layer 5 - PWR "Layer 5 - SW_3V3" (solid, remove dead copper, pour order 82): 1210,810 1210,1635 1170,1675 1075,1770 1075,1860 1075,2610 1130,2665 1510,3045 1670,3045 2575,3045 2645,3115 2655,3125 2695,3125 2860,3125 2940,3045 3710,3045 3785,3120 4880,3120 4940,3060 4940,2750 5015,2675 5015,2290 4940,2215 4940,1525 4940,1460 4540,1060 4005,1060 3920,1060 3895,1035 3895,865 3920,840 3920,735 4020,635 5140,635 5200,695 5225,720 5370,720 5920,720 6000,800 6020,820 6020,2270 5990,2300 5685,2300 5645,2340 5645,2885 5676.06,2916.06 5676.06,3193.94 5645,3225 5420,3450 1200,3450 750,3000 750,870 810,810
"RJ45 GND" on Layer 6 - Bottom Layer "Layer 6 - RJ45_GND" (solid, remove dead copper, pour order 102): 6050,1915 6050,3510 6075,3535 6845,3535 6935,3445 6935,1990 6845,1900 6065,1900
SW_3V3 on Layer 6 - Bottom Layer "Layer 6 - SW_3V3" (solid, remove dead copper, pour order 90): 3324,1719 3324,1685.29 3304.71,1666 3292.71,1654 3267,1654 3226,1654 3197,1625 3197,1550 3196,1549 3229,1549 3251,1571 3252,1572 3269,1572 3294,1597 3295,1597 3328,1630 3328,1643 3346,1661 3346,1715 3342,1719 3324,1719
GND on Layer 6 - Bottom Layer "Layer 6 - GND" (solid, remove dead copper, pour order 114): 20,20 6980,20 6980,3580 20,3580
VDDS_1V8 on Layer 6 - Bottom Layer "BOTTOM-VDDS_1V8 3" (solid, pour order 36): 518 vertices, not listed, extent 2960,1510 3295,1855
VDD_DSP_AVS on Layer 6 - Bottom Layer "BOTTOM-VDD_DSP_AVS" (solid, pour order 38): 3681,1194 3681,1395.99 3688.01,1403 3814,1403 3920,1297 3920,1221 3893,1194 3746,1194 3729,1177 3729,1140 3719,1130 3691,1130 3681,1140

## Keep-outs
Keep-Out Layer:
  text ".Layer_Name" at 577,-858.49 h60

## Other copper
Layer 1 - Top Layer:
  pour cut-out: 754,2273 754,2378 539,2378 539,2273
  pour cut-out: 4645,795 5145,795 5145,1210 4645,1210
  pour cut-out: 6095,2325 6355,2325 6405,2375 6405,2628 6361,2672 6290,2672 6242,2720 6195,2720 6107.19,2807.81 6095,2807.81
  pour cut-out: 3571.89,2929 3828.11,2929 3828.11,3077.85 3571.89,3077.85
  pour cut-out: 3541,2871.31 3541,2670.53 3872,2670.53 3872,2871.31
  pour cut-out: 2704.72,2957.68 2795.28,2957.68 2795.28,3042.32 2704.72,3042.32
  pour cut-out: 1518.55,2757.24 1431.95,2843.85 1431.95,3076.15 1518.57,3162.78 1750.87,3162.78 1837.5,3076.15 1837.5,2843.85 1750.89,2757.24
  pour cut-out: 1125.39,2800.35 1334.06,2800.35 1334.06,2969.65 1125.39,2969.65
  pour cut-out: 1201.14,1011.26 948.86,1011.26 948.86,1188.74 1201.14,1188.74
  region net GND: 1318,1279 1318,1139.73 1330.12,1127.6 1382,1127.6 1382,1279
  pour cut-out: 1282.09,1142.09 1417.91,1142.09 1417.91,1277.91 1282.09,1277.91
  region net GND: 1328,780 1392,780 1392,992 1328,992
  pour cut-out: 1201.14,601.26 948.86,601.26 948.86,778.74 1201.14,778.74
  pour cut-out: 1292.09,784.68 1427.91,784.68 1427.91,991 1292.09,991
  pour cut-out: 2138.07,483.07 2271.93,483.07 2271.93,616.93 2138.07,616.93
  pour cut-out: 2694.68,594.68 2905.32,594.68 2905.32,805.32 2694.68,805.32
  pour cut-out: 3299.08,341.89 3299.08,374.09 3300,375.01 3900.93,375.01 3900.93,341.89
  pour cut-out: 3299.08,458.11 3299.08,425.92 3300,425 3900.93,425 3900.93,458.11
  pour cut-out: 4555.31,2344.68 4555.31,2555.32 4344.69,2555.32 4344.69,2344.68
  pour cut-out: 6095,2325 5695,2325 5695,2875 6095,2875
  region net SYS_3V3: 4374,2445 4305,2445 4262,2402 3990,2402 3977,2415 3977,2542 3980,2545 4225,2545 4235,2535 4235,2490 4250,2475 4374,2475
  region net GND: 3990,2388 3977,2375 3977,2313 3990,2300 4275,2300 4287,2312 4287,2368 4267,2388
  region net VDD_DDR_1V35: 2675,1040 2664.99,1050.01 2560,1050 2550,1040 2550,820 2560,810 2665,810 2675,820
  region net VDDS_1V8: 2675,360 2664.99,349.99 2560,350 2550,360 2550,580 2560,590 2665,590 2675,580
  region net VDD_CORE_AVS: 4110,2575 4099.99,2585.01 4100,2690 4110,2700 4330,2700 4340,2690 4340,2585 4330,2575
  pour cut-out: 2655,1290.39 2655,1420 2986,1751 3258,1751 3346,1839 3346,1997 3456.24,2107.24 3456.24,2141.93 3500,2185.7 3500,2380 3260,2620 1884,2620 1771,2507 1771,1660 1697,1586 1697,1292 1697,1291
  region net SW_3V3: 3615,2721 3607,2729 3536,2729 3450,2815 3450,3100 3440,3110 3400,3110 3390,3100 3390,2795 3505,2680 3605,2680 3615,2690
  region net SYS_3V3: 2805,776 2805,845 2848,888 2848,1170 2838,1180 2715,1180 2705,1170 2705,925 2715,915 2760,915 2775,900 2775,776
  region net GND: 2867,633 2867,767 2723,767 2695,795 2670,795 2550,795 2550,606 2670,606 2670,675 2660,665 2645,665 2630,680 2630,686 2630,740 2645,755 2660,755 2670,745 2681,734 2733,734 2733,686 2681,686 2670,675 2670,606 2696,606 2723,633
  region net GND: 3025,600 3025,640 3015,650 2965,650 2955,660 2955,690 3060,690 3075,675 3075,600 3065,590 3035,590
  region net GND: 4342,2270 4387,2270 4417,2300 4440,2300 4440,2230 4430,2220 4352,2220 4342,2230
  region net GND: 2830,3110 2820,3110 2810,3100 2810,3060 2800,3050 2778,3050 2774,3046 2774,3023 2769,3018 2703,3018 2698,3023 2698,3101 2689,3110 2655,3110 2640,3095 2640,3020 2590,2970 2590,2850 2605,2835 2655,2835 2670,2850 2670,2949 2703,2982 2842,2982 2870,3010 2870,3100 2860,3110
  region net SYS_3V3: 2713,2974 2690,2951 2690,2820 2700,2810 2736,2810 2746,2820 2746,2971 2743,2974
  region net SW_3V3: 2743,3026 2746,3029 2746,3204 2735,3215 2660,3215 2650,3205 2650,3135 2660,3125 2695,3125 2710,3110 2710,3029 2713,3026
  region net GND: 20,20 6980,20 6980,2240 6980,2960 6980,3580 20,3580 20,40 40,40 40,3560 6960,3560 6960,2980 6960,2220 6960,40 20,40
  region net SYS_5V0: 1590,1267.4 1500,1267.4 1480,1247.4 1455,1247.4 1437,1229.4 1393,1229.4 1393,1214.4 1590,1214.4
  region net GND: 1590,1137.4 1500,1137.4 1470,1167.4 1458,1167.4 1437,1188.4 1370,1188.4 1370,1203.4 1590,1203.4
  region net GND: 1600,780 1510,780 1480,810 1468,810 1447,831 1370,831 1370,846 1600,846
  region net SYS_5V0: 1600,910 1510,910 1490,890 1465,890 1447,872 1403,872 1403,857 1600,857
  region net SYS_3V3: 1785,3230 1770,3215 1770,2875 1780,2865 2145,2865 2165,2885 2165,3035 2145,3055 1870,3055 1850,3075 1850,3215 1835,3230
  region net NetC121_1: 1210,2895 1215,2900 1360,2900 1400,2940 1400,3040 1420,3060 1485,3060 1505,3040 1505,2877 1495,2867 1215,2867 1210,2872
  region net BOARD_12V: 830,3210 860,3240 1225,3240 1255,3210 1255,2940 1245,2930 1210,2930 1200,2940 1200,3000 1175,3025 1140,3025 1115,3000 1115,2946 1127,2934 1155,2934 1158,2931 1158,2920 1155,2917 1118,2917 1090,2945 960,2945 920,2905 920,2725 960,2685 1150,2685 1190,2725 1190,2765 1205,2780 1217,2780 1229,2792 1229,2840 1233,2844 1251,2844 1255,2840 1255,2540 1190,2475 895,2475 830,2540
  region net NetD2_2: 510,2965 525,2950 525,2770 510,2755 410,2755 395,2770 395,2950 410,2965
  region net NetC165_1: 115,2830 115,2595 135,2575 590,2575 605,2590 605,2710 590,2725 389.13,2725 264.13,2850 135,2850
  region net GND: 1015,2740 1005,2730 945,2730 935,2740 935,2900 965,2930 1005,2930 1015,2920
  region net GND: 1266,2850 1272,2856 1342,2856 1348,2850 1348,2807 1370,2785 1790,2785 1855,2850 2055,2850 2060,2845 2060,2775 2085,2750 2195,2750 2220,2775 2220,3042 2195,3067 1893,3067 1870,3090 1870,3225 1845,3250 1570,3250 1380,3060 1380,2946 1348,2914 1272,2914 1266,2920 1266,3326 1320,3380 2315,3380 2365,3330 2365,2725 2290,2650 1875,2650 1750,2525 1281,2525 1266,2540
  region net SYS_3V3: 1085,2285 1065,2265 1065,2053 1084,2034 1314,2034 1319,2039 1319,2081 1245,2155 1245,2265 1225,2285
  region net NetL6_2: 1310,2285 1290,2265 1290,2140 1327,2103 1327,2037 1330,2034 1340,2034 1343,2037 1343,2068 1385,2110 1385,2265 1365,2285
  region net GND: 1371,2020 1366,2025 1085,2025 1045,1985 1045,1855 1085,1815 1291,1815 1316,1840 1316,1978 1323,1985 1366,1985 1371,1990
  region net SYS_5V0: 1326,1840 1326,1972 1330,1976 1449,1976 1480,1945 1480,1825 1470,1815 1351,1815
  region net SW_3V3: 5650,1348 5678,1320 5678,1094 5665,1081 5598,1081 5598,1327 5619,1348
  region net GND: 5692,1308 5692,1094 5705,1081 5772,1081 5772,1286 5750,1308
  region net VDD_DDR_1V35: 2219,593 2230,593 2230,620 2242,632 2242,656 2251,665 2290,665 2305,680 2305,810 2290,825 2234,825 2219,810
  region net GND: 2325,810 2340,825 2395,825 2410,810 2410,680 2395,665 2340,665 2325,680
  region net GND: 2090,965 2090,741 2070,721 2070,580 2073.19,576.81 2143.81,576.81 2150,583 2307,583 2325,565 2357,565 2367,555 2367,483 2380,470 2425,470 2440,455 2440,360 2425,345 2355,345 2340,360 2340,440 2315,465 2263,517 2090,517 2084,511 2084,483 2079,478 2027,478 2015,490 2015,955 2025,965
  region net SYS_3V3: 2239,507 2253,507 2315,445 2315,360 2300,345 2205,345 2190,360 2190,390 2205,405 2245,405 2260,420 2260,460 2239,481
  region net NetR23_2: 5520,1584 5520,1614 5528,1622 5538,1622 5543,1627 5543,1643 5538,1648 5514,1648 5509,1643 5509,1584
  region net VDDR_VTT: 1740,1213 1740,1145 1840,1045 2095,1045 2120,1020 2120,740 2140,720 2140,684 2146,678 2170,678 2181,667 2181,642 2199,624 2199,593 2210,593 2210,1020 2235,1045 2513,1045 2610,1141.99 2610,1213 2478,1213 2475,1210 2475,1185 2467.25,1177.25 2372.76,1177.25 2365,1185 2365,1210 2362,1213
  region net NetC168_1: 575,2840 575,2780 635,2720 635,2540 665,2510 800,2510 810,2520 810,2965 795,2980 735,2980 720,2965 720,2885 700,2865 600,2865
  region net GND: 345,2295 360,2310 467.99,2310 482.99,2295 482.99,2272.01 495,2260 540,2260 550,2250 550,2210 540,2200 360,2200 345,2215
  region net VDD_DDR_1V35: 1839,1033 1839,991 1845,985 1990,985 1996,991 1996,1033
  region net VDD_DDR_1V35: 2240,1033 2240,990 2245,985 2346,985 2351,990 2351,1033
  region net GND: 3210,390 3990,390 3990,410 3210,410
  region net NetL12_1: 4526,2484 4639,2484 4650,2495 4650,2535 4640,2545 4557,2545 4526,2514
  region net VDD_DSP_AVS: 4790,2575 4800.01,2585.01 4800,2690 4790,2700 4570,2700 4560,2690 4560,2585 4570,2575
  region net NetL2_1: 4374,2484 4261,2484 4250,2495 4250,2535 4260,2545 4343,2545 4374,2514
  region net GND: 4383,2383 4517,2383 4517,2527 4545,2555 4545,2580 4545,2700 4356,2700 4356,2580 4425,2580 4415,2590 4415,2605 4430,2620 4436,2620 4490,2620 4505,2605 4505,2590 4495,2580 4484,2569 4484,2517 4436,2517 4436,2569 4425,2580 4356,2580 4356,2554 4383,2527
  region net NetL14_1: 2766,776 2766,889 2755,900 2715,900 2705,890 2705,807 2736,776
  region net NetL13_1: 2766,624 2766,511 2755,500 2715,500 2705,510 2705,593 2736,624
  region net GND: 2862,1170 2872,1180 2940,1180 2950,1170 2950,875 2938,863 2882,863 2862,883
  region net SW_3V3: 5548,1627 5548,1643 5552,1647 5552,1823 5535,1840 5535,1915 5555,1935 5600,1935 5620,1915 5620,1815 5585,1780 5585,1634 5573,1622 5553,1622
  region net GND: 5538,1668 5538,1811.88 5515,1834.88 5515,1915 5495,1935 5450,1935 5430,1915 5430,1835 5500,1765 5500,1673 5505,1668
  region net SW_3V3: 5665,2330 5665,2250 5715,2250 5715,2330
  region net GND: 5733.07,2330 5733.07,2250 5783.07,2250 5783.07,2330
  region net GND: 5692.34,2870 5692.34,2950 5742.34,2950 5742.34,2870
  region net SW_3V3: 5619.13,2870 5619.13,2950 5669.13,2950 5669.13,2870
  region net GND: 2862,230 2872,220 2940,220 2950,230 2950,525 2938,537 2882,537 2862,517
  region net SYS_3V3: 2805,624 2805,555 2848,512 2848,230 2838,220 2715,220 2705,230 2705,475 2715,485 2760,485 2775,500 2775,624
  region net GND: 4910,2388 4923,2375 4923,2313 4910,2300 4625,2300 4613,2312 4613,2368 4633,2388
  region net SYS_3V3: 4526,2445 4595,2445 4638,2402 4910,2402 4923,2415 4923,2542 4920,2545 4675,2545 4665,2535 4665,2490 4650,2475 4526,2475
  pour cut-out: 5369.02,1357 5620,1357 5620,1607 5370,1607
  pour cut-out: 5716.5,1387.09 5903.5,1387.09 5903.5,1522.91 5716.5,1522.91
  region net GND: 539,2302 539,2263 578,2263 578,2302
  text ".Layer_Name" at 577,-858.49 h60
Layer 2 - GND:
  pour cut-out: 6095,2325 5695,2325 5695,2875 6095,2875
  text ".Layer_Name" at 577,-858.49 h60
